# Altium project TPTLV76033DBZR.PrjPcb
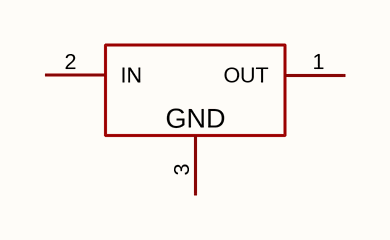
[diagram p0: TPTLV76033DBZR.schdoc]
1 sheet, 1 parts. Net scope: global (net labels, ports and power ports of the same name join across sheets).

## Sheet TPTLV76033DBZR.schdoc
size 127 x 101 mm

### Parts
U?  tptlv76033dbzr  [SOT-23-3_L2.9-W1.3-P1.90-LS2.4-BR]  (value not drawn)

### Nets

Not connected (* = marked no-connect by the designer): U? 1(OUT) 2(IN) 3(GND)

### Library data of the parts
U? = tptlv76033dbzr: 输出极性:正极;工作电压:30V;输出电压:3.3V;输出电流:100mA;电源纹波抑制比(PSRR):49dB@(120Hz);输出类型:固定;; Manufacturer: TECH PUBLIC(台舟); AddInBom: yes; ModelId: c62791f0466c4ae2a892c056b845b0ca; ModelName: SOT-23-3P_L2.9-W1.3-H1.0-LS2.4-P0.95; ModelTransform: 98.425,114.173,0,180,0,0,0.0005,-0.0005,0; Output Configuration: 正极; Voltage - Supply: 30V; Output Voltage: 3.3V; Output Current: 100mA; Voltage Dropout: 2V@(100mA); standby current: 3mA; Noise: 40uV; Output Type: 固定; Number of Outputs: 1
